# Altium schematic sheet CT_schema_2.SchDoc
size 283 x 174 mm
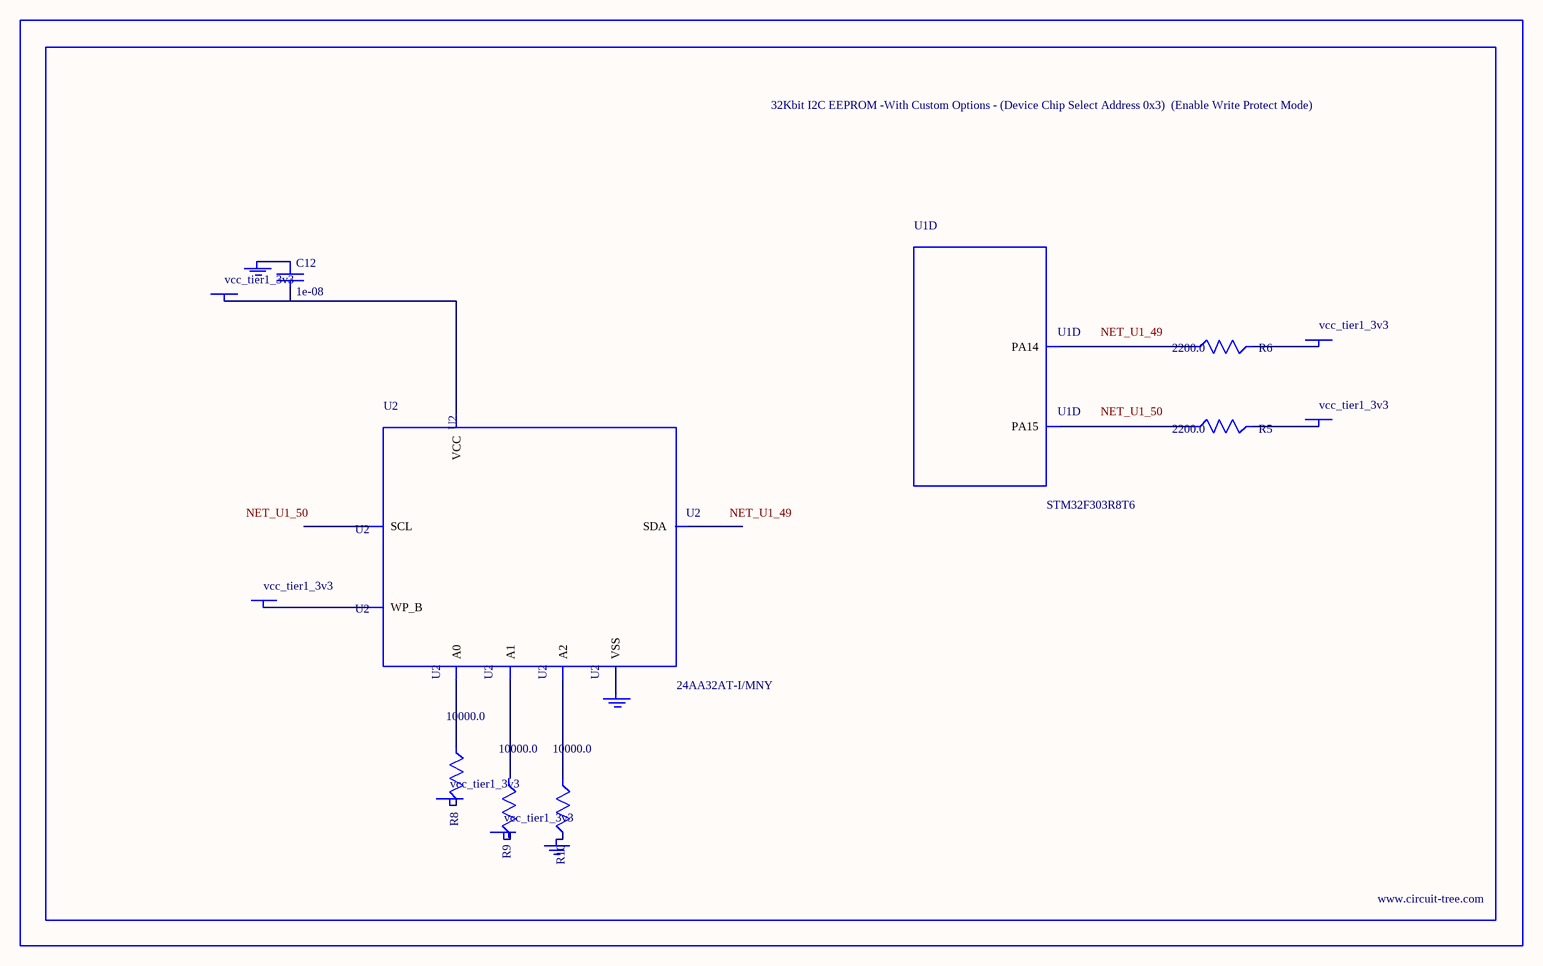
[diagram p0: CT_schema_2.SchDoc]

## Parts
BORDER1  (no value)
C12  1e-08  [C0402]
GND_INSTANCE_1_0  (no value)
GND_INSTANCE_1_1  (no value)
GND_INSTANCE_1_2  (no value)
POWER_INSTANCE_1_0  vcc_tier1_3v3
POWER_INSTANCE_1_1  vcc_tier1_3v3
POWER_INSTANCE_1_2  vcc_tier1_3v3
POWER_INSTANCE_1_3  vcc_tier1_3v3
POWER_INSTANCE_1_4  vcc_tier1_3v3
POWER_INSTANCE_1_5  vcc_tier1_3v3
R5  2200.0  [R0603]
R6  2200.0  [R0603]
R8  10000.0  [R0603]
R9  10000.0  [R0603]
R10  10000.0  [R0603]
U1  STM32F303R8T6  [LQFP64]  (part D of 5)
U2  24AA32AT-I/MNY  [TDFN-8/6MM]

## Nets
NetC12_1: C12.1 GND_INSTANCE_1_1.0(GND)
NetC12_2: C12.2 POWER_INSTANCE_1_3.0(PWR) U2.8(VCC)
NetGND_INSTANCE_1_0_0: GND_INSTANCE_1_0.0(GND) R10.2
NetGND_INSTANCE_1_2_0: GND_INSTANCE_1_2.0(GND) U2.4(VSS)
NetPOWER_INSTANCE_1_0_0: POWER_INSTANCE_1_0.0(PWR) R8.2
NetPOWER_INSTANCE_1_2_0: POWER_INSTANCE_1_2.0(PWR) U2.7(WP_B)
NetPOWER_INSTANCE_1_4_0: POWER_INSTANCE_1_4.0(PWR) R6.2
NetPOWER_INSTANCE_1_5_0: POWER_INSTANCE_1_5.0(PWR) R5.2
NetR5_1: R5.1 U1.50(PA15)
NetR6_1: R6.1 U1.49(PA14)
NetR8_1: R8.1 U2.1(A0)
NetR10_1: R10.1 U2.3(A2)

Not connected (* = marked no-connect by the designer): POWER_INSTANCE_1_1 0(PWR); R9 1 2; U2 2(A1) 5(SDA) 6(SCL)

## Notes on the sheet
- Labels drawn without touching a wire or pin: NET_U1_49, NET_U1_50

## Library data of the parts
BORDER1 = BORDER_PAGE1
C12 = C0402C103K3RAC
GND_INSTANCE_1_0-GND_INSTANCE_1_2 = GND
POWER_INSTANCE_1_0-POWER_INSTANCE_1_5 = PWR
R5 R6 = RC0603JR-072K2L
R8-R10 = RC0603JR-0710KL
